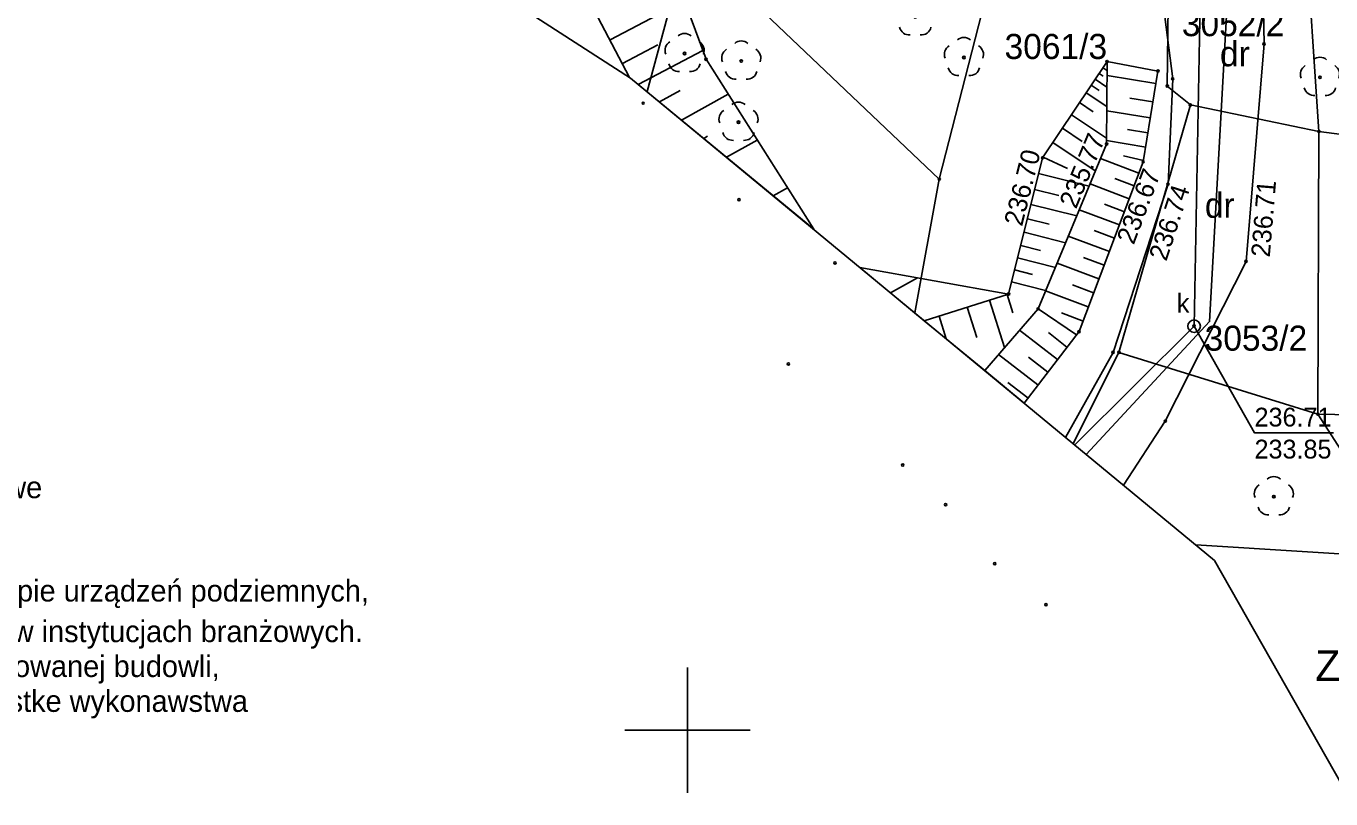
# Model space of a CAD drawing. Extents: x 6596400 to 6597200, y 5539751 to 5540251.
# Drawn here: x 6596673.6 to 6596725.7, y 5540048.3 to 5540079.1 of the extents above; entities that cross this region are included whole.
import ezdxf

# ---------------------------------------------------------------- set-up
doc = ezdxf.new("R2010")
doc.units = 0
for name, color, linetype in [('000 Inne (niezydentyfikowane)', 7, 'Continuous'), ('140-Punkty robocze', 7, 'Continuous'), ('203-punkt graniczny', 7, 'Continuous'), ('210-oznaczenie konturu użytku gruntowego', 7, 'Continuous'), ('211-numer działki ewidencyjnej', 7, 'Continuous'), ('217-kontur klasyfikacyjny', 7, 'Continuous'), ('218-kontur użytku gruntowego', 7, 'Continuous'), ('219-działka ewidencyjna', 7, 'Continuous'), ('996-Tekst dodatkowy mały', 7, 'Continuous'), ('drzewo liściaste', 7, 'Continuous'), ('jezdnia', 7, 'Continuous'), ('Linia obszaru zagospodarowania terenu', 7, 'Continuous'), ('Opis obszaru zagospodarowania terenu', 7, 'Continuous'), ('pikieta sztuczna', 7, 'Continuous'), ('pikieta sztuczna-Atr2', 7, 'Continuous'), ('przewód kanalizacyjny', 7, 'Continuous'), ('rzedna', 7, 'Continuous'), ('rzedna-Atr2', 7, 'Continuous'), ('rzedna-Atr3', 7, 'Continuous'), ('skarpa nieumocniona', 7, 'Continuous'), ('Strefa korytarza ekologicznego', 7, 'Continuous'), ('Wstawianie ramki sekcyjnej z opisem', 7, 'Continuous'), ('właz do komory lub kanału - okrągły', 7, 'Continuous'), ('właz do komory lub kanału - okrągły-Atr17', 7, 'Continuous'), ('Zakres', 7, 'Continuous')]:
    doc.layers.add(name, color=color, linetype=linetype)

# ---------------------------------------------------------------- blocks, each defined once
blk = doc.blocks.new('203')
blk.add_circle((0, 0), 0.045)
blk = doc.blocks.new('PW01')
blk.add_circle((0, 0), 0.045)
blk = doc.blocks.new('US22')
blk.add_circle((0, 0), 0.25)
blk = doc.blocks.new('OP021')
blk.add_circle((0, 0), 0.05)
for centre, start, end in [((0, 0.4), 49.272, 130.728), ((-0.38, 0.124), 121.308, 202.548), ((0.38, 0.124), 337.452, 58.692), ((-0.235, -0.324), 193.221, 274.871), ((0.235, -0.324), 265.129, 346.779)]:
    blk.add_arc(centre, 0.4, start, end)
blk = doc.blocks.new('RAMKA500K')
for p, q in [((300, 48.5), (300, 53.5)), ((297.5, 51), (302.5, 51))]:
    blk.add_line(p, q)
blk = doc.blocks.new('PIKIETA')
blk.add_circle((0, 0), 0.045)

msp = doc.modelspace()

# ---------------------------------------------------------------- linework, layer by layer
at = {"layer": '000 Inne (niezydentyfikowane)'}
for p, q in [((6596696.91, 5540078.52), (6596699.88, 5540080.08)), ((6596697.4, 5540077.58), (6596698.82, 5540078.33)), ((6596698.033, 5540076.75), (6596700.61, 5540078.1)), ((6596716.25, 5540076.95), (6596716.72, 5540076.64)), ((6596716.41, 5540077.18), (6596716.57, 5540077.08)), ((6596716.56, 5540077.41), (6596716.73, 5540077.3)), ((6596718.68, 5540076.79), (6596716.73, 5540077.1)), ((6596698.881, 5540076.049), (6596699.71, 5540076.51)), ((6596715.9, 5540076.41), (6596716.72, 5540075.86)), ((6596716.1, 5540076.72), (6596716.41, 5540076.51)), ((6596699.756, 5540075.326), (6596701.62, 5540076.36)), ((6596715.63, 5540076.02), (6596716.18, 5540075.66)), ((6596718.56, 5540076.05), (6596717.64, 5540076.2)), ((6596715.31, 5540075.54), (6596716.71, 5540074.6)), ((6596718.45, 5540075.41), (6596716.72, 5540075.69)), ((6596714.95, 5540075), (6596715.74, 5540074.47)), ((6596718.36, 5540074.81), (6596717.54, 5540074.95)), ((6596700.644, 5540074.593), (6596700.8, 5540074.68)), ((6596701.547, 5540073.847), (6596702.78, 5540074.53)), ((6596714.57, 5540074.43), (6596716.26, 5540073.3)), ((6596718.27, 5540074.25), (6596716.71, 5540074.51)), ((6596714.18, 5540073.84), (6596715.15, 5540073.4)), ((6596718, 5540073.21), (6596716.47, 5540073.79)), ((6596718.18, 5540073.72), (6596717.39, 5540073.9)), ((6596714, 5540073.19), (6596716.01, 5540072.69)), ((6596717.61, 5540072.19), (6596716.05, 5540072.78)), ((6596717.81, 5540072.71), (6596717.04, 5540073)), ((6596703.417, 5540072.302), (6596703.99, 5540072.62)), ((6596713.84, 5540072.56), (6596714.8, 5540072.32)), ((6596713.69, 5540071.96), (6596715.52, 5540071.51)), ((6596717.22, 5540071.15), (6596715.62, 5540071.75)), ((6596717.42, 5540071.67), (6596716.63, 5540071.97)), ((6596713.55, 5540071.39), (6596714.42, 5540071.17)), ((6596713.42, 5540070.85), (6596715.07, 5540070.43)), ((6596716.82, 5540070.08), (6596715.18, 5540070.7)), ((6596717.02, 5540070.62), (6596716.21, 5540070.92)), ((6596713.29, 5540070.33), (6596714.08, 5540070.13)), ((6596713.16, 5540069.83), (6596714.67, 5540069.45)), ((6596716.61, 5540069.54), (6596715.79, 5540069.85)), ((6596713.04, 5540069.35), (6596713.76, 5540069.17)), ((6596716.4, 5540068.99), (6596714.74, 5540069.62)), ((6596708.092, 5540068.44), (6596709.17, 5540069.04)), ((6596712.92, 5540068.88), (6596714.28, 5540068.53)), ((6596716.19, 5540068.44), (6596715.35, 5540068.75)), ((6596712.04, 5540068.15), (6596712.64, 5540066.26)), ((6596712.74, 5540068.37), (6596712.97, 5540067.64)), ((6596715.98, 5540067.88), (6596714.28, 5540068.52)), ((6596711.15, 5540067.87), (6596711.54, 5540066.65)), ((6596715.51, 5540066.76), (6596713.98, 5540067.8)), ((6596715.77, 5540067.31), (6596714.91, 5540067.64)), ((6596710.03, 5540067.51), (6596710.318, 5540066.602)), ((6596714.75, 5540065.78), (6596713.24, 5540066.95)), ((6596715.13, 5540066.27), (6596714.39, 5540066.85)), ((6596713.97, 5540064.77), (6596712.4, 5540065.98)), ((6596714.37, 5540065.28), (6596713.6, 5540065.87)), ((6596713.57, 5540064.25), (6596712.77, 5540064.86))]:
    msp.add_line(p, q, dxfattribs=at)
at = {"layer": '217-kontur klasyfikacyjny'}
for points in [[(6596710.04, 5540072.97), (6596689.99, 5540092.03)], [(6596709.067, 5540067.635), (6596710.04, 5540072.97)], [(6596717.2, 5540066.06), (6596715.371, 5540062.428)], [(6596725.14, 5540063.6), (6596717.2, 5540066.06)], [(6596734.44, 5540049.18), (6596725.14, 5540063.6)]]:
    msp.add_lwpolyline(points, dxfattribs=at)
at = {"layer": '218-kontur użytku gruntowego'}
for points in [[(6596710.04, 5540072.97), (6596689.99, 5540092.03)], [(6596689.99, 5540092.03), (6596710.04, 5540072.97)], [(6596710.04, 5540072.97), (6596712.64, 5540083.14)], [(6596712.64, 5540083.14), (6596710.04, 5540072.97)], [(6596719.21, 5540083.11), (6596719.13, 5540076.68)], [(6596719.13, 5540076.68), (6596719.21, 5540083.11)], [(6596724.63, 5540083.07), (6596725.18, 5540074.87)], [(6596725.18, 5540074.87), (6596724.63, 5540083.07)], [(6596719.13, 5540076.68), (6596720.05, 5540075.93)], [(6596720.05, 5540075.93), (6596719.13, 5540076.68)], [(6596720.05, 5540075.93), (6596717.2, 5540066.06)], [(6596717.2, 5540066.06), (6596720.05, 5540075.93)], [(6596725.18, 5540074.87), (6596720.05, 5540075.93)], [(6596720.05, 5540075.93), (6596725.18, 5540074.87)], [(6596725.14, 5540063.6), (6596725.18, 5540074.87)], [(6596725.18, 5540074.87), (6596725.14, 5540063.6)], [(6596725.18, 5540074.87), (6596731.78, 5540074)], [(6596731.78, 5540074), (6596725.18, 5540074.87)], [(6596709.067, 5540067.635), (6596710.04, 5540072.97)], [(6596710.04, 5540072.97), (6596709.067, 5540067.635)], [(6596717.2, 5540066.06), (6596715.371, 5540062.428)], [(6596715.371, 5540062.428), (6596717.2, 5540066.06)], [(6596725.14, 5540063.6), (6596717.2, 5540066.06)], [(6596717.2, 5540066.06), (6596725.14, 5540063.6)], [(6596734.44, 5540049.18), (6596725.14, 5540063.6)], [(6596731.23, 5540063.48), (6596725.14, 5540063.6)], [(6596725.14, 5540063.6), (6596734.44, 5540049.18)], [(6596725.14, 5540063.6), (6596731.23, 5540063.48)]]:
    msp.add_lwpolyline(points, dxfattribs=at)
at = {"layer": '219-działka ewidencyjna'}
for points in [[(6596710.04, 5540072.97), (6596689.99, 5540092.03)], [(6596710.04, 5540072.97), (6596712.64, 5540083.14)], [(6596719.13, 5540076.68), (6596719.21, 5540083.11)], [(6596725.18, 5540074.87), (6596724.63, 5540083.07)], [(6596720.05, 5540075.93), (6596719.13, 5540076.68)], [(6596717.2, 5540066.06), (6596720.05, 5540075.93)], [(6596725.18, 5540074.87), (6596720.05, 5540075.93)], [(6596725.14, 5540063.6), (6596725.18, 5540074.87)], [(6596731.78, 5540074), (6596725.18, 5540074.87)], [(6596709.067, 5540067.635), (6596710.04, 5540072.97)], [(6596715.371, 5540062.428), (6596717.2, 5540066.06)], [(6596725.14, 5540063.6), (6596717.2, 5540066.06)], [(6596725.14, 5540063.6), (6596731.23, 5540063.48)], [(6596734.44, 5540049.18), (6596725.14, 5540063.6)]]:
    msp.add_lwpolyline(points, dxfattribs=at)
at = {"layer": 'jezdnia'}
for points in [[(6596722.99, 5540078.36), (6596722.83, 5540086.31), (6596724.29, 5540088.47), (6596720.02, 5540089.23), (6596715.92, 5540090.16), (6596716.5, 5540087.55), (6596718.57, 5540083.05), (6596719.35, 5540076.97), (6596719.16, 5540072.77), (6596716.97, 5540066.06), (6596715.072, 5540062.675)], [(6596717.387, 5540060.763), (6596719.05, 5540063.32), (6596722.27, 5540069.69), (6596722.99, 5540078.36)]]:
    msp.add_lwpolyline(points, dxfattribs=at)
at = {"layer": 'Linia obszaru zagospodarowania terenu'}
msp.add_lwpolyline([(6596720.263, 5540058.387), (6596728.96, 5540057.84), (6596731.45, 5540057.76), (6596731.02, 5540064.64), (6596745.49, 5540064.58), (6596746.99, 5540056.99), (6596772.84, 5540062.25), (6596786.21, 5540064.83), (6596807.99, 5540057.58), (6596818.837, 5540049.192)], dxfattribs=at)
at = {"layer": 'przewód kanalizacyjny'}
for points in [[(6596723.203, 5540121.052), (6596721.45, 5540104.04), (6596720.5, 5540082.91), (6596720.2, 5540067.11), (6596715.44, 5540062.371)], [(6596724.65, 5540121.069), (6596722.94, 5540105.56), (6596720.82, 5540067.29), (6596715.895, 5540061.995)]]:
    msp.add_lwpolyline(points, dxfattribs=at)
at = {"layer": 'rzedna-Atr2'}
msp.add_lwpolyline([(6596720.2, 5540067.11), (6596722.61, 5540062.85), (6596725.756, 5540062.85)], dxfattribs=at)
at = {"layer": 'skarpa nieumocniona'}
for points in [[(6596678.95, 5540103.44), (6596684.48, 5540100.39), (6596694.1, 5540088.97), (6596698.32, 5540084.27), (6596700.74, 5540077.75), (6596705.03, 5540070.97), (6596697.73, 5540077), (6596697.69, 5540077.02), (6596691.51, 5540088.79), (6596684.27, 5540099.42), (6596679.14, 5540103.03), (6596675.06, 5540106.16)], [(6596678.95, 5540103.44), (6596684.48, 5540100.39), (6596694.1, 5540088.97), (6596698.32, 5540084.27), (6596700.74, 5540077.75), (6596705.03, 5540070.97), (6596697.73, 5540077), (6596697.69, 5540077.02), (6596691.51, 5540088.79), (6596684.27, 5540099.42), (6596679.14, 5540103.03), (6596675.06, 5540106.16)], [(6596716.71, 5540074.37), (6596713.98, 5540067.8), (6596711.85, 5540065.34), (6596709.44, 5540067.32), (6596712.8, 5540068.39), (6596714.16, 5540073.82), (6596716.73, 5540077.66)], [(6596716.71, 5540074.37), (6596713.98, 5540067.8), (6596711.85, 5540065.34), (6596709.44, 5540067.32), (6596712.8, 5540068.39), (6596714.16, 5540073.82), (6596716.73, 5540077.66)], [(6596718.76, 5540077.28), (6596718.17, 5540073.66), (6596715.61, 5540066.89), (6596713.42, 5540064.04), (6596711.85, 5540065.34), (6596713.98, 5540067.8), (6596716.71, 5540074.37), (6596716.73, 5540077.66)], [(6596718.76, 5540077.28), (6596718.17, 5540073.66), (6596715.61, 5540066.89), (6596713.42, 5540064.04), (6596711.85, 5540065.34), (6596713.98, 5540067.8), (6596716.71, 5540074.37), (6596716.73, 5540077.66)], [(6596712.8, 5540068.39), (6596709.44, 5540067.32), (6596706.87, 5540069.45)], [(6596712.8, 5540068.39), (6596709.44, 5540067.32), (6596706.87, 5540069.45)]]:
    msp.add_lwpolyline(points, close=True, dxfattribs=at)
at = {"layer": 'Strefa korytarza ekologicznego'}
msp.add_lwpolyline([(6596698.383, 5540076.46), (6596706.03, 5540104.75), (6596710.01, 5540120.89)], dxfattribs=at)
at = {"layer": 'Zakres'}
msp.add_lwpolyline([(6596822.22, 5540097.5), (6596800.39, 5540105.4), (6596755.76, 5540121.45), (6596697.73, 5540120.74), (6596659.35, 5540133.92), (6596647.64, 5540109.28), (6596697.73, 5540077), (6596721.01, 5540057.77), (6596727.72, 5540045.95), (6596731.95, 5540033.61), (6596741.17, 5540031.18), (6596755.59, 5540029.2), (6596757.85, 5540044.22), (6596787.25, 5540055.04), (6596806.3, 5540048.33), (6596813.97, 5540042.6), (6596833.15, 5540068.58), (6596822.3, 5540077.75)], close=True, dxfattribs=at)

# ---------------------------------------------------------------- block references
at = {"layer": '140-Punkty robocze'}
for p in [(6596699.88, 5540077.98), (6596722.99, 5540078.36), (6596700.74, 5540077.75), (6596702.14, 5540077.68), (6596711.02, 5540077.82), (6596716.73, 5540077.66), (6596718.76, 5540077.28), (6596719.35, 5540076.97), (6596725.22, 5540077.03), (6596698.23, 5540076), (6596702.03, 5540075.24), (6596716.71, 5540074.37), (6596714.16, 5540073.82), (6596718.17, 5540073.66), (6596719.16, 5540072.77), (6596702.05, 5540072.15), (6596705.88, 5540069.63), (6596722.27, 5540069.69), (6596712.8, 5540068.39), (6596713.98, 5540067.8), (6596715.61, 5540066.89), (6596716.97, 5540066.06), (6596704.02, 5540065.6), (6596719.05, 5540063.32), (6596708.58, 5540061.57), (6596723.38, 5540060.31), (6596710.29, 5540059.99), (6596712.25, 5540057.64), (6596714.29, 5540056)]:
    msp.add_blockref('PIKIETA', p, dxfattribs=at)
at = {"layer": '203-punkt graniczny'}
for p in [(6596719.13, 5540076.68), (6596720.05, 5540075.93), (6596725.18, 5540074.87), (6596710.04, 5540072.97), (6596717.2, 5540066.06), (6596725.14, 5540063.6)]:
    msp.add_blockref('203', p, dxfattribs=at)
at = {"layer": 'drzewo liściaste'}
for p in [(6596709.08, 5540079.44), (6596699.88, 5540077.98), (6596702.14, 5540077.68), (6596711.02, 5540077.82), (6596725.22, 5540077.03), (6596702.03, 5540075.24), (6596723.38, 5540060.31)]:
    msp.add_blockref('OP021', p, dxfattribs=at)
at = {"layer": 'pikieta sztuczna'}
for p in [(6596716.71, 5540074.37), (6596714.16, 5540073.82), (6596718.17, 5540073.66), (6596719.16, 5540072.77), (6596722.27, 5540069.69)]:
    msp.add_blockref('PW01', p, dxfattribs=at)
at = {"layer": 'rzedna'}
msp.add_blockref('PW01', (6596720.2, 5540067.11), dxfattribs=at)
at = {"layer": 'Wstawianie ramki sekcyjnej z opisem'}
msp.add_blockref('RAMKA500K', (6596400, 5540000), dxfattribs=at)
at = {"layer": 'właz do komory lub kanału - okrągły'}
msp.add_blockref('US22', (6596720.2, 5540067.11), dxfattribs=at)

# ---------------------------------------------------------------- texts
at = {"layer": '210-oznaczenie konturu użytku gruntowego'}
for p in [(6596721.23, 5540077.47), (6596720.63, 5540071.43)]:
    msp.add_text('dr', height=1, dxfattribs=at).set_placement(p)
at = {"layer": '211-numer działki ewidencyjnej'}
for s, p in [('3052/2', (6596719.71, 5540078.67)), ('3061/3', (6596712.64, 5540077.76)), ('3053/2', (6596720.62, 5540066.13))]:
    msp.add_text(s, height=1, dxfattribs=at).set_placement(p)
at = {"layer": '996-Tekst dodatkowy mały'}
for s, p in [('obszar zagrożony podtopieniem przez wody powodziowe', (6596645.11, 5540060.25)), ('Nie wyklucza się istnienia w terenie innych nie wykazancyh na niniejszej mapie urządzeń podziemnych,', (6596634.5, 5540056.13)), ('które nie były zgłoszone do inwentaryzacji lub o których brak jest informacji w instytucjach branżowych.', (6596634.52, 5540054.51)), ('Warunkiem rozpoczęcia prac budowlanych jest wytyczenie w terenie projektowanej budowli,', (6596634.38, 5540053.12)), ('a po jej zakończeniu wykonanie inwentaryzacji powykonawczej przez jednostke wykonawstwa', (6596634.48, 5540051.73))]:
    msp.add_text(s, height=0.862, dxfattribs=at).set_placement(p)
at = {"layer": 'Opis obszaru zagospodarowania terenu'}
msp.add_text('ZE43', height=1.225, dxfattribs=at).set_placement((6596725.03, 5540052.96))
at = {"layer": 'pikieta sztuczna-Atr2'}
for s, rotation, p in [('235.77', 67.436, (6596715.493, 5540071.752)), ('236.70', 75.939, (6596713.338, 5540071.058)), ('236.67', 69.286, (6596717.792, 5540070.325)), ('236.71', 85.253, (6596723.217, 5540069.838)), ('236.74', 71.924, (6596719.093, 5540069.667))]:
    msp.add_text(s, height=0.75, rotation=rotation, dxfattribs=at).set_placement(p)
at = {"layer": 'rzedna-Atr2'}
msp.add_text('236.71', height=0.75, dxfattribs=at).set_placement((6596722.61, 5540063.107))
at = {"layer": 'rzedna-Atr3'}
msp.add_text('233.85', height=0.75, dxfattribs=at).set_placement((6596722.61, 5540061.832))
at = {"layer": 'właz do komory lub kanału - okrągły-Atr17'}
msp.add_text('k', height=0.75, dxfattribs=at).set_placement((6596719.51, 5540067.65))

doc.saveas('drawing.dxf')
